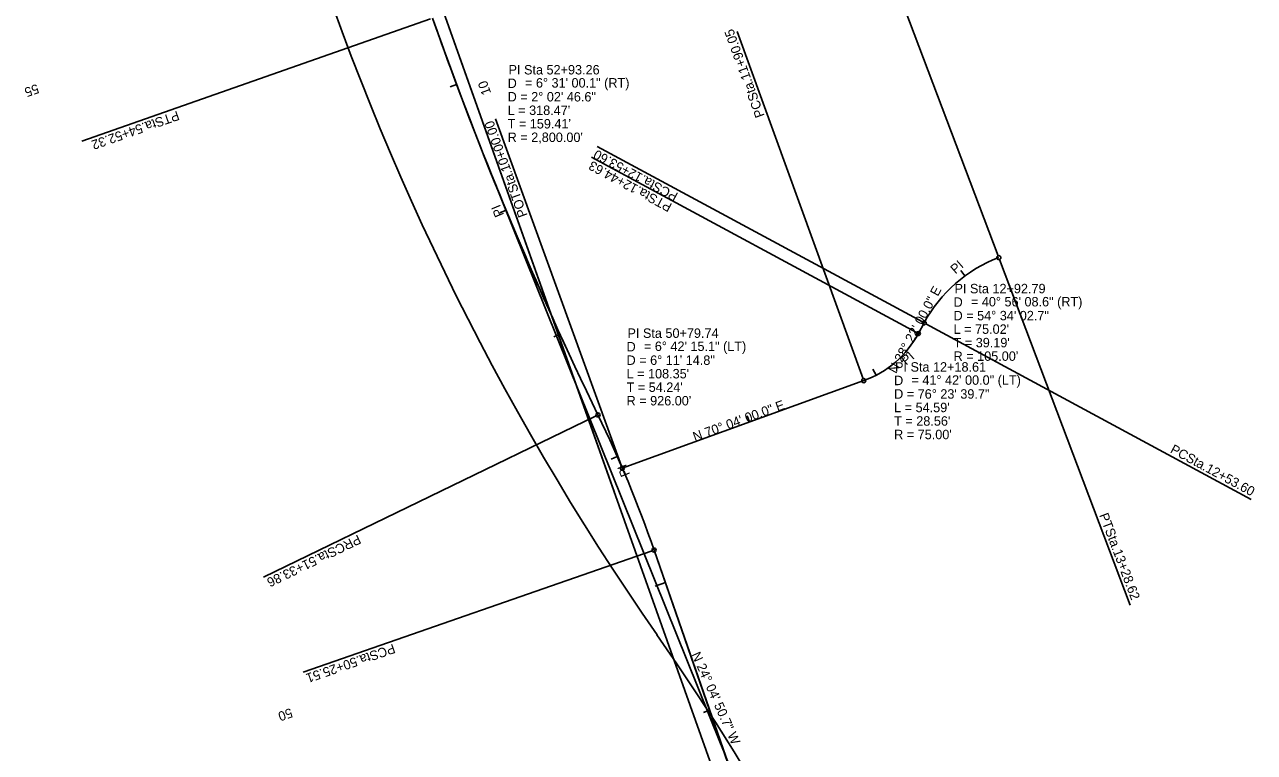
# Model space of a CAD drawing. Extents: x 1615740 to 1617154, y 899624 to 904812.
# Drawn here: x 1615906 to 1616816, y 903398 to 903937 of the extents above; entities that cross this region are included whole.
import ezdxf

# ---------------------------------------------------------------- set-up
doc = ezdxf.new("R2010")
doc.units = 0
for name, color, linetype in [('Default', 7, 'Continuous'), ('Exist Plan Preparation Drainage Flow Arrows', 7, 'Continuous'), ('Exist Plan Preparation Drainage Notes Label', 7, 'Continuous'), ('Exist Structure Minor Pipes CMP 15 Inch Text', 7, 'Continuous'), ('Exist Structure Minor Pipes CMP 24 Inch Text', 7, 'Continuous'), ('Exist Structure Minor Pipes RCP 12 Inch Text', 7, 'Continuous'), ('Exist Structure Minor Pipes RCP 24 Inch Text', 7, 'Continuous'), ('Prop Plan Preparation Sag', 7, 'Continuous'), ('Scratch_Level_7', 7, 'Continuous')]:
    doc.layers.add(name, color=color, linetype=linetype)

msp = doc.modelspace()

# ---------------------------------------------------------------- linework, layer by layer
at = {"layer": 'Default'}
for p, q in [((1616561.34, 902975.04), (1616086.7, 904309.23)), ((1616561.34, 902975.04), (1616086.7, 904309.23)), ((1616342.41, 903590.45), (1616086.73, 904309.16)), ((1616561.75, 902997.95), (1616371.68, 903547.96)), ((1616525.22, 903106.46), (1616371.68, 903547.96))]:
    msp.add_line(p, q, dxfattribs=at)
for centre, radius, start, end in [((1618016.2, 904626.61), 2000, 179.21665, 214.80209), ((1618849.35, 904870.2), 2800, 199.3643, 204.77008), ((1614731.69, 902343.63), 2000, 347.74, 34.80849)]:
    msp.add_arc(centre, radius, start, end, dxfattribs=at)
at = {"layer": 'Exist Plan Preparation Drainage Flow Arrows'}
for p, q in [((1616348.19, 903608.56), (1616345.46, 903616.08)), ((1616348.19, 903608.56), (1616345.46, 903616.08)), ((1616348.19, 903608.56), (1616345.46, 903616.08)), ((1616348.19, 903608.56), (1616345.46, 903616.08)), ((1616380.06, 903523.87), (1616372.5, 903521.24)), ((1616380.06, 903523.87), (1616372.5, 903521.24)), ((1616380.06, 903523.87), (1616372.5, 903521.24)), ((1616380.06, 903523.87), (1616372.5, 903521.24))]:
    msp.add_line(p, q, dxfattribs=at)
at = {"layer": 'Exist Plan Preparation Drainage Notes Label'}
for p, q in [((1616225.56, 903892.59), (1616220.88, 903890.85)), ((1616225.56, 903892.59), (1616220.88, 903890.85)), ((1616225.56, 903892.59), (1616220.88, 903890.85)), ((1616225.56, 903892.59), (1616220.88, 903890.85)), ((1616262.14, 903799.53), (1616257.52, 903797.62)), ((1616262.14, 903799.53), (1616257.52, 903797.62)), ((1616262.14, 903799.53), (1616257.52, 903797.62)), ((1616262.14, 903799.53), (1616257.52, 903797.62)), ((1616601.75, 903750.84), (1616598.78, 903754.86)), ((1616601.75, 903750.84), (1616598.78, 903754.86)), ((1616601.75, 903750.84), (1616598.78, 903754.86)), ((1616601.75, 903750.84), (1616598.78, 903754.86)), ((1616302.02, 903707.83), (1616297.47, 903705.75)), ((1616302.02, 903707.83), (1616297.47, 903705.75)), ((1616302.02, 903707.83), (1616297.47, 903705.75)), ((1616302.02, 903707.83), (1616297.47, 903705.75)), ((1616535.96, 903677.35), (1616533.64, 903681.79)), ((1616535.96, 903677.35), (1616533.64, 903681.79)), ((1616535.96, 903677.35), (1616533.64, 903681.79)), ((1616535.96, 903677.35), (1616533.64, 903681.79)), ((1616442.2, 903642.65), (1616440.49, 903647.35)), ((1616442.2, 903642.65), (1616440.49, 903647.35)), ((1616442.2, 903642.65), (1616440.49, 903647.35)), ((1616442.2, 903642.65), (1616440.49, 903647.35)), ((1616344.41, 903617.26), (1616339.83, 903615.24)), ((1616344.41, 903617.26), (1616339.83, 903615.24)), ((1616344.41, 903617.26), (1616339.83, 903615.24)), ((1616344.41, 903617.26), (1616339.83, 903615.24)), ((1616412.91, 903429.42), (1616408.18, 903427.78)), ((1616412.91, 903429.42), (1616408.18, 903427.78)), ((1616412.91, 903429.42), (1616408.18, 903427.78)), ((1616412.91, 903429.42), (1616408.18, 903427.78))]:
    msp.add_line(p, q, dxfattribs=at)
at = {"layer": 'Exist Structure Minor Pipes CMP 24 Inch Text'}
for p, q in [((1616251.87, 903824.71), (1616420.36, 903406.09)), ((1616567.27, 903708.22), (1616571.54, 903716.12)), ((1616348.19, 903608.56), (1616526.85, 903673.35)), ((1616525.22, 903106.46), (1616371.68, 903547.96))]:
    msp.add_line(p, q, dxfattribs=at)
for centre, radius, start, end in [((1618849.35, 904870.2), 2800, 199.3643, 205.88101), ((1616663.93, 903666.23), 105, 110.69761, 151.63333), ((1616501.28, 903743.86), 75, 289.93333, 331.63333), ((1615497.06, 903243.78), 926, 19.17682, 25.88101), ((1613080.73, 902061.89), 3600, 19.57069, 21.92481)]:
    msp.add_arc(centre, radius, start, end, dxfattribs=at)
at = {"layer": 'Exist Structure Minor Pipes RCP 12 Inch Text'}
msp.add_line((1616561.34, 902975.02), (1616086.69, 904309.48), dxfattribs=at)
at = {"layer": 'Prop Plan Preparation Sag'}
for p, q in [((1616626.29, 903765.86), (1616529.62, 904021.7)), ((1616206.34, 903941.29), (1615948.31, 903850.61)), ((1616526.34, 903674.76), (1616433.1, 903931.87)), ((1616526.34, 903674.76), (1616433.1, 903931.87)), ((1616526.34, 903674.76), (1616433.1, 903931.87)), ((1616526.34, 903674.76), (1616433.1, 903931.87)), ((1616347.68, 903609.97), (1616254.43, 903867.08)), ((1616347.68, 903609.97), (1616254.43, 903867.08)), ((1616347.68, 903609.97), (1616254.43, 903867.08)), ((1616347.68, 903609.97), (1616254.43, 903867.08)), ((1616570.22, 903716.83), (1616329.56, 903846.77)), ((1616565.96, 903708.94), (1616325.3, 903838.88)), ((1616565.96, 903708.94), (1616325.3, 903838.88)), ((1616565.96, 903708.94), (1616325.3, 903838.88)), ((1616565.96, 903708.94), (1616325.3, 903838.88)), ((1616627.35, 903763.05), (1616724.01, 903507.2)), ((1616627.35, 903763.05), (1616724.01, 903507.2)), ((1616627.35, 903763.05), (1616724.01, 903507.2)), ((1616572.86, 903715.4), (1616813.52, 903585.46)), ((1616572.86, 903715.4), (1616813.52, 903585.46)), ((1616572.86, 903715.4), (1616813.52, 903585.46)), ((1616328.84, 903647.33), (1616082.77, 903527.95)), ((1616328.84, 903647.33), (1616082.77, 903527.95)), ((1616328.84, 903647.33), (1616082.77, 903527.95)), ((1616328.84, 903647.33), (1616082.77, 903527.95)), ((1616370.26, 903547.47), (1616111.94, 903457.63)), ((1616370.26, 903547.47), (1616111.94, 903457.63)), ((1616370.26, 903547.47), (1616111.94, 903457.63)), ((1616370.26, 903547.47), (1616111.94, 903457.63))]:
    msp.add_line(p, q, dxfattribs=at)
for centre in [(1616626.82, 903764.45), (1616626.82, 903764.45), (1616626.82, 903764.45), (1616626.82, 903764.45), (1616571.54, 903716.12), (1616571.54, 903716.12), (1616571.54, 903716.12), (1616571.54, 903716.12), (1616567.27, 903708.22), (1616567.27, 903708.22), (1616567.27, 903708.22), (1616567.27, 903708.22), (1616526.85, 903673.35), (1616526.85, 903673.35), (1616526.85, 903673.35), (1616526.85, 903673.35), (1616330.19, 903647.99), (1616330.19, 903647.99), (1616330.19, 903647.99), (1616330.19, 903647.99), (1616348.19, 903608.56), (1616348.19, 903608.56), (1616348.19, 903608.56), (1616348.19, 903608.56), (1616371.68, 903547.96), (1616371.68, 903547.96), (1616371.68, 903547.96), (1616371.68, 903547.96)]:
    msp.add_circle(centre, 1.5, dxfattribs=at)

# ---------------------------------------------------------------- texts
at = {"layer": 'Default'}
for rotation, p in [(112.62265, (1616260.79, 903796.16)), (112.62265, (1616260.79, 903796.16)), (41.16547, (1616594.73, 903751.94)), (41.16547, (1616594.73, 903751.94)), (40.78333, (1616558.28, 903684.4)), (40.78333, (1616558.28, 903684.4)), (112.52892, (1616354.05, 903603.95)), (112.52892, (1616354.05, 903603.95))]:
    msp.add_text('PI ', height=7, rotation=rotation, dxfattribs=at).set_placement(p)
at = {"layer": 'Exist Structure Minor Pipes CMP 15 Inch Text'}
for s, rotation, p in [('N 28%%d 22\' 00.0" E', 61.63333, (1616550.77, 903678.08)), ('N 28%%d 22\' 00.0" E', 61.63333, (1616550.77, 903678.08)), ('N 70%%d 04\' 00.0" E', 19.93333, (1616401.91, 903628.25)), ('N 70%%d 04\' 00.0" E', 19.93333, (1616401.91, 903628.25)), ('N 24%%d 04\' 50.7" W', 294.08074, (1616399.18, 903470.67)), ('N 24%%d 04\' 50.7" W', 294.08074, (1616399.18, 903470.67))]:
    msp.add_text(s, height=7, rotation=rotation, dxfattribs=at).set_placement(p)
at = {"layer": 'Exist Structure Minor Pipes RCP 24 Inch Text'}
for s, p in [('PI Sta 52+93.26', (1616264, 903900)), ('PI Sta 52+93.26', (1616264, 903900)), ('PI Sta 52+93.26', (1616264, 903900)), ('PI Sta 52+93.26', (1616264, 903900)), ('= 6%%d 31\' 00.1" (RT)', (1616276.18, 903890.3)), ('= 6%%d 31\' 00.1" (RT)', (1616276.18, 903890.3)), ('= 6%%d 31\' 00.1" (RT)', (1616276.18, 903890.3)), ('= 6%%d 31\' 00.1" (RT)', (1616276.18, 903890.3)), ('D', (1616263.33, 903890)), ('D', (1616263.33, 903890)), ('D', (1616263.33, 903890)), ('D', (1616263.33, 903890)), ('D = 2%%d 02\' 46.6"', (1616263.33, 903880)), ('D = 2%%d 02\' 46.6"', (1616263.33, 903880)), ('D = 2%%d 02\' 46.6"', (1616263.33, 903880)), ('D = 2%%d 02\' 46.6"', (1616263.33, 903880)), ("L = 318.47'", (1616263.33, 903870)), ("L = 318.47'", (1616263.33, 903870)), ("L = 318.47'", (1616263.33, 903870)), ("L = 318.47'", (1616263.33, 903870)), ("T = 159.41'", (1616263.33, 903860)), ("T = 159.41'", (1616263.33, 903860)), ("T = 159.41'", (1616263.33, 903860)), ("T = 159.41'", (1616263.33, 903860)), ("R = 2,800.00'", (1616263.33, 903850)), ("R = 2,800.00'", (1616263.33, 903850)), ("R = 2,800.00'", (1616263.33, 903850)), ("R = 2,800.00'", (1616263.33, 903850)), ('PI Sta 12+92.79', (1616594, 903738)), ('PI Sta 12+92.79', (1616594, 903738)), ('D', (1616593.33, 903728)), ('D', (1616593.33, 903728)), ('= 40%%d 56\' 08.6" (RT)', (1616606.18, 903728.3)), ('= 40%%d 56\' 08.6" (RT)', (1616606.18, 903728.3)), ('D = 54%%d 34\' 02.7"', (1616593.33, 903718)), ('D = 54%%d 34\' 02.7"', (1616593.33, 903718)), ('PI Sta 50+79.74', (1616352, 903705)), ('PI Sta 50+79.74', (1616352, 903705)), ('PI Sta 50+79.74', (1616352, 903705)), ('PI Sta 50+79.74', (1616352, 903705)), ("L = 75.02'", (1616593.33, 903708)), ("L = 75.02'", (1616593.33, 903708)), ('D', (1616351.33, 903695)), ('D', (1616351.33, 903695)), ('D', (1616351.33, 903695)), ('D', (1616351.33, 903695)), ('= 6%%d 42\' 15.1" (LT)', (1616364.18, 903695.3)), ('= 6%%d 42\' 15.1" (LT)', (1616364.18, 903695.3)), ('= 6%%d 42\' 15.1" (LT)', (1616364.18, 903695.3)), ('= 6%%d 42\' 15.1" (LT)', (1616364.18, 903695.3)), ("T = 39.19'", (1616593.33, 903698)), ("T = 39.19'", (1616593.33, 903698)), ('D = 6%%d 11\' 14.8"', (1616351.33, 903685)), ('D = 6%%d 11\' 14.8"', (1616351.33, 903685)), ('D = 6%%d 11\' 14.8"', (1616351.33, 903685)), ('D = 6%%d 11\' 14.8"', (1616351.33, 903685)), ("R = 105.00'", (1616593.33, 903688)), ("R = 105.00'", (1616593.33, 903688)), ("L = 108.35'", (1616351.33, 903675)), ("L = 108.35'", (1616351.33, 903675)), ("L = 108.35'", (1616351.33, 903675)), ("L = 108.35'", (1616351.33, 903675)), ('PI Sta 12+18.61', (1616550, 903680)), ('PI Sta 12+18.61', (1616550, 903680)), ("T = 54.24'", (1616351.33, 903665)), ("T = 54.24'", (1616351.33, 903665)), ("T = 54.24'", (1616351.33, 903665)), ("T = 54.24'", (1616351.33, 903665)), ('D', (1616549.33, 903670)), ('D', (1616549.33, 903670)), ('= 41%%d 42\' 00.0" (LT)', (1616562.18, 903670.3)), ('= 41%%d 42\' 00.0" (LT)', (1616562.18, 903670.3)), ("R = 926.00'", (1616351.33, 903655)), ("R = 926.00'", (1616351.33, 903655)), ("R = 926.00'", (1616351.33, 903655)), ("R = 926.00'", (1616351.33, 903655)), ('D = 76%%d 23\' 39.7"', (1616549.33, 903660)), ('D = 76%%d 23\' 39.7"', (1616549.33, 903660)), ("L = 54.59'", (1616549.33, 903650)), ("L = 54.59'", (1616549.33, 903650)), ("T = 28.56'", (1616549.33, 903640)), ("T = 28.56'", (1616549.33, 903640)), ("R = 75.00'", (1616549.33, 903630)), ("R = 75.00'", (1616549.33, 903630))]:
    msp.add_text(s, height=7, dxfattribs=at).set_placement(p)
at = {"layer": 'Prop Plan Preparation Sag'}
for s, rotation, p in [('PCSta.11+90.05', 109.93333, (1616453.59, 903869.49)), ('PCSta.11+90.05', 109.93333, (1616453.59, 903869.49)), ('PCSta.11+90.05', 109.93333, (1616453.59, 903869.49)), ('PCSta.11+90.05', 109.93333, (1616453.59, 903869.49)), ('PTSta.54+52.32', 199.3643, (1616018.8, 903873.26)), ('POTSta.10+00.00', 109.93333, (1616278.18, 903795.73)), ('POTSta.10+00.00', 109.93333, (1616278.18, 903795.73)), ('POTSta.10+00.00', 109.93333, (1616278.18, 903795.73)), ('POTSta.10+00.00', 109.93333, (1616278.18, 903795.73)), ('PCSta.12+53.60', 151.63333, (1616390, 903811.86)), ('PTSta.12+44.63', 151.63333, (1616385.59, 903804.05)), ('PTSta.12+44.63', 151.63333, (1616385.59, 903804.05)), ('PTSta.12+44.63', 151.63333, (1616385.59, 903804.05)), ('PTSta.12+44.63', 151.63333, (1616385.59, 903804.05)), ('PCSta.12+53.60', 331.63333, (1616753.08, 903620.37)), ('PCSta.12+53.60', 331.63333, (1616753.08, 903620.37)), ('PCSta.12+53.60', 331.63333, (1616753.08, 903620.37)), ('PTSta.13+28.62', 290.69761, (1616700.97, 903573.84)), ('PTSta.13+28.62', 290.69761, (1616700.97, 903573.84)), ('PTSta.13+28.62', 290.69761, (1616700.97, 903573.84)), ('PRCSta.51+33.86', 205.88101, (1616152.56, 903559.59)), ('PRCSta.51+33.86', 205.88101, (1616152.56, 903559.59)), ('PRCSta.51+33.86', 205.88101, (1616152.56, 903559.59)), ('PRCSta.51+33.86', 205.88101, (1616152.56, 903559.59)), ('PCSta.50+25.51', 199.17682, (1616178.6, 903478.69)), ('PCSta.50+25.51', 199.17682, (1616178.6, 903478.69)), ('PCSta.50+25.51', 199.17682, (1616178.6, 903478.69)), ('PCSta.50+25.51', 199.17682, (1616178.6, 903478.69))]:
    msp.add_text(s, height=7, rotation=rotation, dxfattribs=at).set_placement(p)
at = {"layer": 'Scratch_Level_7'}
for s, rotation, p in [('55', 199.3643, (1615914.92, 903893.12)), ('55', 199.3643, (1615914.92, 903893.12)), ('55', 199.3643, (1615914.92, 903893.12)), ('55', 199.3643, (1615914.92, 903893.12)), ('10', 109.93333, (1616251.2, 903886.27)), ('10', 109.93333, (1616251.2, 903886.27)), ('10', 109.93333, (1616251.2, 903886.27)), ('10', 109.93333, (1616251.2, 903886.27)), ('50', 199.17682, (1616102.65, 903431.1)), ('50', 199.17682, (1616102.65, 903431.1)), ('50', 199.17682, (1616102.65, 903431.1)), ('50', 199.17682, (1616102.65, 903431.1))]:
    msp.add_text(s, height=7, rotation=rotation, dxfattribs=at).set_placement(p)

doc.saveas('drawing.dxf')
